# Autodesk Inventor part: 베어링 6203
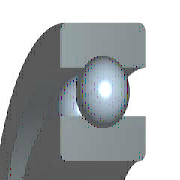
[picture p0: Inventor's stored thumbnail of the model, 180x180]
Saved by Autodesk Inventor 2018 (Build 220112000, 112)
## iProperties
IsCustomPart: 0
Created: 2009-02
Part Number: 베어링 6203
Material: 강철, 연강
Description: 깊은 그루브 볼 베어링
Document SubType Name: Modeling
Standard: KS B 2023
Standards Organization: KS
Language: ko-KR
Size Designation: 6203 - 17 x 40 x 12
Categories: <MemberInstance><Categories><Category DisplayName="샤프트 부품" InternalName="7f7aeb1f-a693-4053-b835-cee3144e0d98" Mnemonic="SHFT"><Category DisplayName="베어링" Inter
Density: 1 g/cm^3
Appearance: 밝은 황색
Author: pww
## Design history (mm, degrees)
sketch "스케치" dims "d0" = 5.98 (= -0.26 x WD + 0.26 x BD)
  geometry: L1 (3.01, 14.25)-(8.99, 14.25); L2 (6, 14.25)-(6, 11.26); L3 (6, 14.25)-(6, 17.24); L4 (3.778, 12.249)-(0, 12.249); L5 (0, 8.5)-(12, 8.5); L6 (3.778, 16.251)-(0, 16.251); L7 (0, 20)-(12, 20); L8 (12, 8.5)-(12, 12.249); L9 (8.222, 12.249)-(12, 12.249); L10 (8.222, 16.251)-(12, 16.251); L11 (12, 20)-(12, 16.251); L12 (-1.4, 0)-(8.4, 0) reference; L13 (0, -0.3)-(0, 5.3) reference
  constraints: 22 end point, 4 point on line, 2 collinear, 2 perpendicular, 2 symmetric about line, 1 midpoint, 1 parallel, 14 other
  dimensions: "d9" = 17 diameter of L5 L12 (= WD); "d11" = 40 diameter of L7 L12 (= BD); "d12" = 12 distance between parallel lines of L8 L13 (= KB); "d13" = 24.498 diameter of L9 L12 (= 0.326 x BD + 0.674 x WD)
revolve "본체" stored, may be unused: angle "d6" = 90 deg
revolve "볼" stored, may be unused: angle "d7" = 90 deg
pattern_circular "IDS_ARRAYBALL[SIMPL:T]" dims angle "d3" = 360 deg
body "Solid1"
fillet "모깎기1" dims "d1" = 0.6 (= KRS)
other parameters: "WD" = 17 [user parameter; used in 5 equation terms], "BD" = 40 [user parameter; used in 5 equation terms], "KB" = 12 [user parameter; used in 1 equation term], "KRS" = 0.6 [user parameter; used in 1 equation term], "d4" = 0, "d5" = 0, "d8" = 0, "d14" = 0, "d15" = 0, "BBA" = 0 [user parameter], "BC0" = 4750000 [user parameter], "BC" = 9560000 [user parameter], "WR" = 8.5 (= 0.5 x WD) [user parameter]
